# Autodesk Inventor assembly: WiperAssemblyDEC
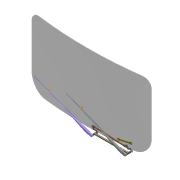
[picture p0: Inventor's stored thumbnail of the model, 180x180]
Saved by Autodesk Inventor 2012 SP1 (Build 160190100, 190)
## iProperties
Created: 2006-03
Part Number: WiperAssemblyDEC
Document SubType Name: Assembly
Designer: debonom
Author: debonom
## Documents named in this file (9)
- D:\Backup\Autodesk Motion Files\Inv2012DynSim\WiperAssemblyDEC.iam
- D:\Backup\Autodesk Motion Files\Inv2012DynSim\Parts\Bearings.ipt
- D:\Backup\Autodesk Motion Files\Inv2012DynSim\Sub-Assemblies\Motor_Crank_Asm.iam
- D:\Backup\Autodesk Motion Files\Inv2012DynSim\Sub-Assemblies\Complete_wiper_left_asm.iam
- D:\Backup\Autodesk Motion Files\Inv2012DynSim\Sub-Assemblies\Complete_wiper_right_asm.iam
- D:\Backup\Autodesk Motion Files\Inv2012DynSim\Parts\Crank_motor2.ipt
- D:\Backup\Autodesk Motion Files\Inv2012DynSim\Parts\Inter_Crank.ipt
- D:\Backup\Autodesk Motion Files\Inv2012DynSim\Parts\Windscreen.ipt
- D:\Backup\Autodesk Motion Files\Inv2012DynSim\Sub-Assemblies\Brush_asm_left.iam
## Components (8 placed, 8 different names)
1. Bearings:1 — Mate:1, Mate:2, Mate:3, Mate:9, Mate:11
2. Windscreen:1 — Mate:1, Mate:2, Mate:3
3. Motor_Crank_Asm:1 [sub-assembly]
4. Brush_asm_left:1 [sub-assembly] — Mate:4, Mate:5, Angle:2
5. Complete_wiper_left_asm:1 [sub-assembly] — Mate:4, Mate:5, Angle:2
6. Complete_wiper_right_asm:1 [sub-assembly] — Mate:9, Mate:11
7. Crank_motor2:1
8. Inter_Crank:1
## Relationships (8: Mate 7, Angle 1)
- Mate:1: Bearings:1 ↔ Windscreen:1
- Mate:2: Bearings:1 ↔ Windscreen:1
- Mate:3: Bearings:1 ↔ Windscreen:1
- Mate:4: Brush_asm_left:1 ↔ Complete_wiper_left_asm:1
- Mate:5: Brush_asm_left:1 ↔ Complete_wiper_left_asm:1
- Angle:2: Brush_asm_left:1 ↔ Complete_wiper_left_asm:1
- Mate:9: Bearings:1 ↔ Complete_wiper_right_asm:1
- Mate:11: Bearings:1 ↔ Complete_wiper_right_asm:1
